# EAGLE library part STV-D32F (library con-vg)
CONNECTOR male, 32 pins, type D, rows AC, grid 5.08 mm
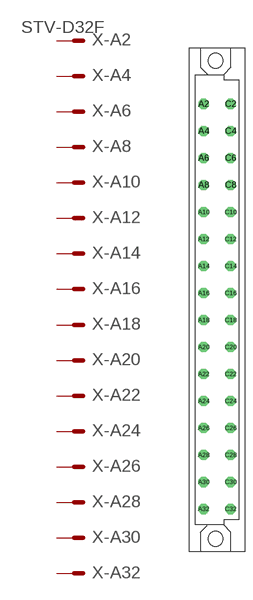
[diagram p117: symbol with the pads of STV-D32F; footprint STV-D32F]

Designator prefix X; gates -A2=MVAL -A4=MAL -A6=MAL -A8=MAL -A10=MAL -A12=MAL -A14=MAL -A16=MAL -A18=MAL -A20=MAL -A22=MAL -A24=MAL -A26=MAL -A28=MAL -A30=MAL -A32=MAL -C2=MVAL -C4=MAL -C6=MAL -C8=MAL -C10=MAL -C12=MAL -C14=MAL -C16=MAL -C18=MAL -C20=MAL -C22=MAL -C24=MAL -C26=MAL -C28=MAL -C30=MAL -C32=MAL

## STV-D32F  [STV-D32F]
A2  -A2:S  pas
A4  -A4:S  pas
A6  -A6:S  pas
A8  -A8:S  pas
A10  -A10:S  pas
A12  -A12:S  pas
A14  -A14:S  pas
A16  -A16:S  pas
A18  -A18:S  pas
A20  -A20:S  pas
A22  -A22:S  pas
A24  -A24:S  pas
A26  -A26:S  pas
A28  -A28:S  pas
A30  -A30:S  pas
A32  -A32:S  pas
C2  -C2:S  pas
C4  -C4:S  pas
C6  -C6:S  pas
C8  -C8:S  pas
C10  -C10:S  pas
C12  -C12:S  pas
C14  -C14:S  pas
C16  -C16:S  pas
C18  -C18:S  pas
C20  -C20:S  pas
C22  -C22:S  pas
C24  -C24:S  pas
C26  -C26:S  pas
C28  -C28:S  pas
C30  -C30:S  pas
C32  -C32:S  pas

## Footprint STV-D32F (pad centres in mm)
CONNECTOR male, 32 pins, type D, rows AC, grid 5.08 mm
drill 1.3 octagon: A2 -2.54,36.83; A4 -2.54,31.75; A6 -2.54,26.67; A8 -2.54,21.59; A10 -2.54,16.51; A12 -2.54,11.43; A14 -2.54,6.35; A16 -2.54,1.27; A18 -2.54,-3.81; A20 -2.54,-8.89; A22 -2.54,-13.97; A24 -2.54,-19.05; A26 -2.54,-24.13; A28 -2.54,-29.21; A30 -2.54,-34.29; A32 -2.54,-39.37; C2 2.54,36.83; C4 2.54,31.75; C6 2.54,26.67; C8 2.54,21.59; C10 2.54,16.51; C12 2.54,11.43; C14 2.54,6.35; C16 2.54,1.27; C18 2.54,-3.81; C20 2.54,-8.89; C22 2.54,-13.97; C24 2.54,-19.05; C26 2.54,-24.13; C28 2.54,-29.21; C30 2.54,-34.29; C32 2.54,-39.37
hole 2.8 at -0.3,45
hole 2.8 at -0.3,-45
